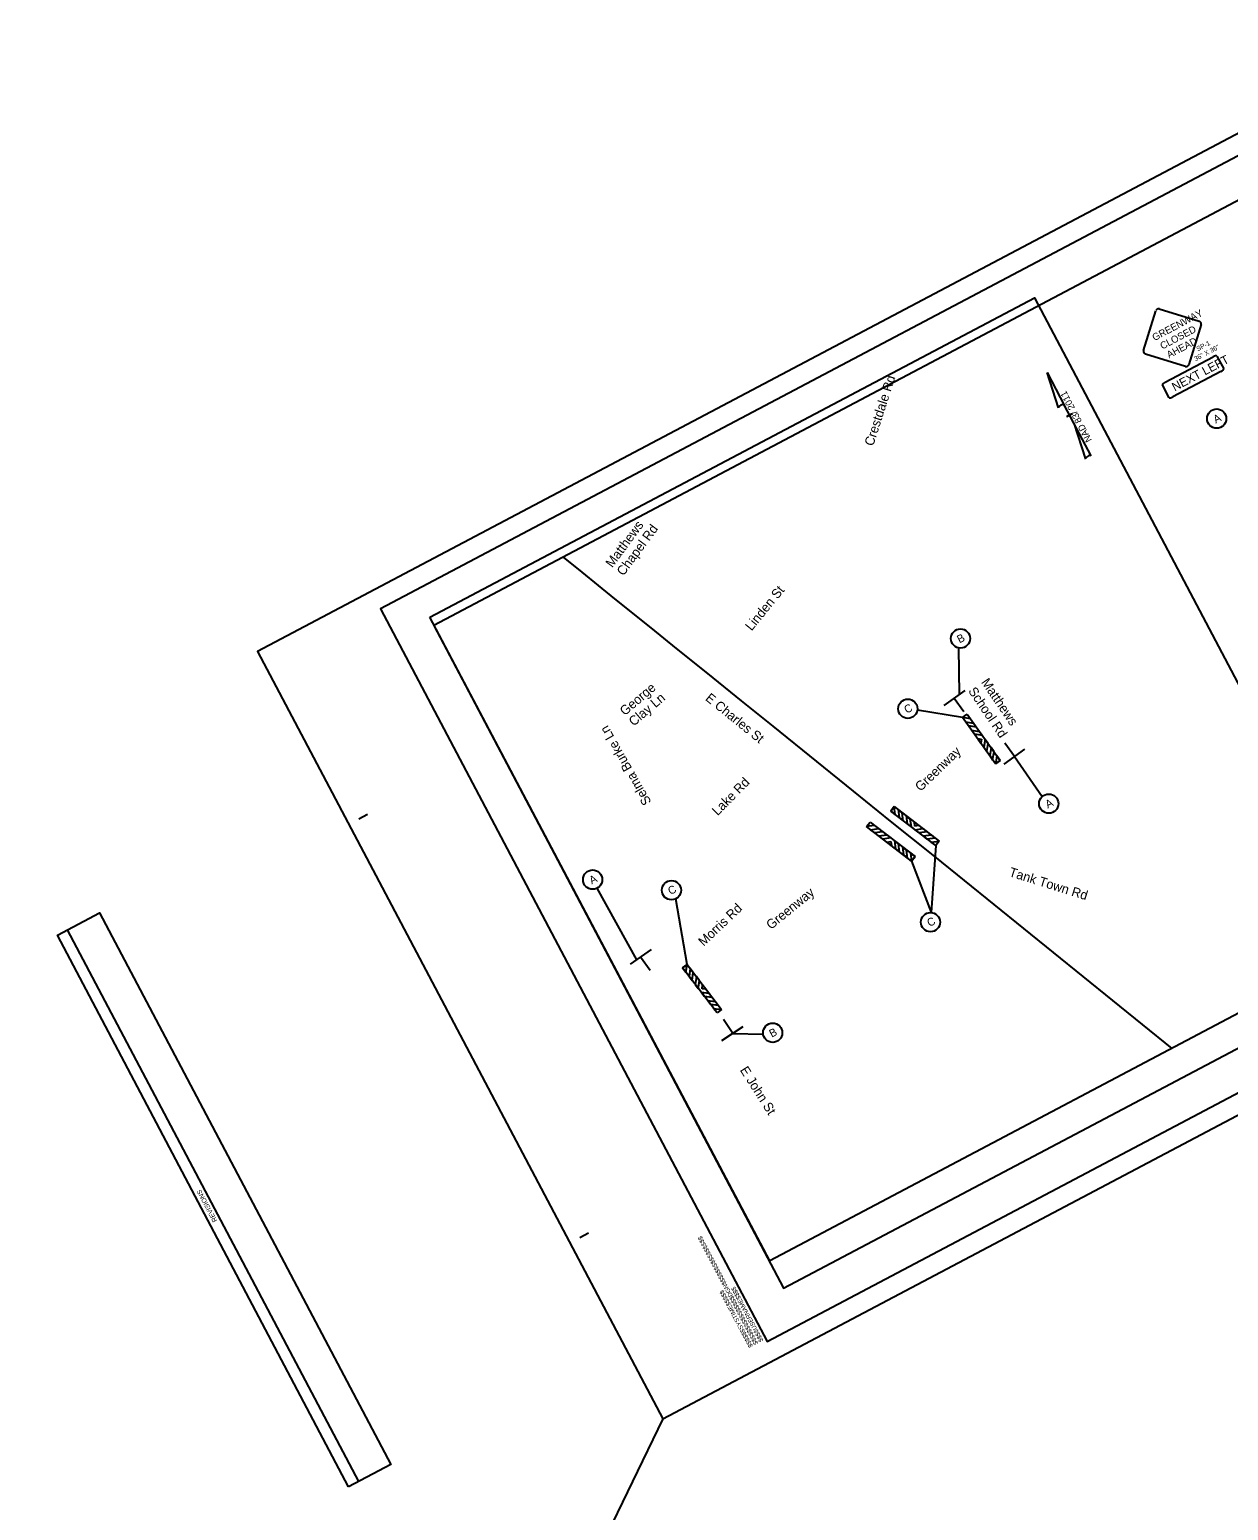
# Model space of a CAD drawing. Extents: x 1485914 to 1489436, y 493744 to 499689.
# Drawn here: x 1487141 to 1488661, y 497812 to 499689 of the extents above; entities that cross this region are included whole.
import ezdxf

# ---------------------------------------------------------------- set-up
doc = ezdxf.new("R2010")
doc.units = 0
for name, color, linetype in [('Default', 7, 'Continuous'), ('DEV BORDER CELL', 7, 'Continuous'), ('DEV STATIONARY SIGN CELL', 7, 'Continuous'), ('DEV TYPE 3 BARRICADE CELL', 7, 'Continuous'), ('Gray Area Fill Shapes', 7, 'Continuous'), ('Old_Level_10', 7, 'Continuous'), ('Prop North Arrow NAD83 for Plan Sheets CELL', 7, 'Continuous'), ('Scratch_Level_0', 7, 'Continuous'), ('Scratch_Level_6', 7, 'Continuous'), ('Sheet Block Revision CELL', 7, 'Continuous'), ('Sheet Plot Border Outside CELL', 7, 'Continuous'), ('WS SP-200 CELL', 7, 'Continuous'), ('WS SP-4L CELL', 7, 'Continuous'), ('WZ OSDR CELL', 7, 'Continuous')]:
    doc.layers.add(name, color=color, linetype=linetype)

msp = doc.modelspace()

# ---------------------------------------------------------------- linework, layer by layer
at = {"layer": 'DEV BORDER CELL'}
for p, q in [((1487586.4, 498954.8), (1487586.4, 498954.8)), ((1487558.1, 498688.3), (1487569.2, 498694.1)), ((1487838.3, 498157.7), (1487849.3, 498163.5)), ((1488075.8, 498025.9), (1488075.8, 498025.9))]:
    msp.add_line(p, q, dxfattribs=at)
msp.add_lwpolyline([(1488912, 499654.8), (1487585.5, 498954.4), (1488075.8, 498025.9), (1489402.2, 498726.3)], close=True, dxfattribs=at)
at = {"layer": 'DEV STATIONARY SIGN CELL'}
for p, q in [((1488326.3, 498850.7), (1488299.9, 498831.9)), ((1488313, 498841.2), (1488325.1, 498824.1)), ((1488376.1, 498757.6), (1488402.5, 498776.4)), ((1488389.4, 498767.1), (1488377.2, 498784.2)), ((1487928.5, 498522.8), (1487902.1, 498504.1)), ((1487915.2, 498513.4), (1487927.3, 498496.3)), ((1488032.1, 498416.1), (1488020.6, 498433.7)), ((1488018.4, 498407.2), (1488045.5, 498424.9))]:
    msp.add_line(p, q, dxfattribs=at)
at = {"layer": 'DEV TYPE 3 BARRICADE CELL'}
for p, q in [((1488323.6, 498816.5), (1488329.5, 498820.7)), ((1488323.6, 498816.5), (1488329.5, 498820.7)), ((1488333.6, 498815), (1488323.6, 498816.5)), ((1488365.4, 498758), (1488323.6, 498816.5)), ((1488327.4, 498811.3), (1488337.4, 498809.7)), ((1488331.1, 498806), (1488327.4, 498811.3)), ((1488329.5, 498820.7), (1488333.6, 498815)), ((1488329.5, 498820.7), (1488371.2, 498762.1)), ((1488341.1, 498804.4), (1488331.1, 498806)), ((1488337.4, 498809.7), (1488341.1, 498804.4)), ((1488334.9, 498800.7), (1488344.9, 498799.1)), ((1488338.6, 498795.5), (1488334.9, 498800.7)), ((1488348.6, 498793.9), (1488338.6, 498795.5)), ((1488342.4, 498790.2), (1488347.5, 498789.4)), ((1488346.2, 498784.9), (1488342.4, 498790.2)), ((1488342.8, 498789.6), (1488346.6, 498784.3)), ((1488344.9, 498799.1), (1488348.6, 498793.9)), ((1488347.5, 498789.4), (1488346.6, 498784.3)), ((1488352.1, 498789), (1488350.3, 498779)), ((1488355.9, 498783.7), (1488352.1, 498789)), ((1488350.3, 498779), (1488354.1, 498773.8)), ((1488354.1, 498773.8), (1488355.9, 498783.7)), ((1488359.6, 498778.5), (1488357.9, 498768.5)), ((1488357.9, 498768.5), (1488361.6, 498763.2)), ((1488363.4, 498773.2), (1488359.6, 498778.5)), ((1488361.6, 498763.2), (1488363.4, 498773.2)), ((1488367.1, 498767.9), (1488365.4, 498758)), ((1488371.2, 498762.1), (1488367.1, 498767.9)), ((1488371.2, 498762.1), (1488365.4, 498758)), ((1488365.4, 498758), (1488371.2, 498762.1)), ((1488232.4, 498698.1), (1488236.8, 498703.8)), ((1488236.8, 498703.8), (1488232.4, 498698.1)), ((1488289.5, 498654.3), (1488232.4, 498698.1)), ((1488232.4, 498698.1), (1488238, 498693.8)), ((1488236.8, 498703.8), (1488293.9, 498660)), ((1488238, 498693.8), (1488236.8, 498703.8)), ((1488241.9, 498699.9), (1488243.2, 498689.8)), ((1488247.1, 498695.9), (1488241.9, 498699.9)), ((1488248.3, 498685.9), (1488247.1, 498695.9)), ((1488252.2, 498692), (1488253.4, 498681.9)), ((1488257.3, 498688), (1488252.2, 498692)), ((1488201.9, 498678.4), (1488206.2, 498684.1)), ((1488201.9, 498678.4), (1488206.2, 498684.1)), ((1488211.9, 498679.8), (1488201.9, 498678.4)), ((1488258.9, 498634.6), (1488201.9, 498678.4)), ((1488206.2, 498684.1), (1488211.9, 498679.8)), ((1488206.2, 498684.1), (1488263.3, 498640.3)), ((1488207, 498674.4), (1488217, 498675.8)), ((1488212.1, 498670.5), (1488207, 498674.4)), ((1488217, 498675.8), (1488222.1, 498671.9)), ((1488243.2, 498689.8), (1488248.3, 498685.9)), ((1488253.4, 498681.9), (1488258.6, 498678)), ((1488258.6, 498678), (1488257.3, 498688)), ((1488267.6, 498680.2), (1488262.5, 498684.1)), ((1488263.1, 498679), (1488262.5, 498684.1)), ((1488263.1, 498683.6), (1488268.2, 498679.7)), ((1488268.2, 498679.7), (1488263.1, 498679)), ((1488263.3, 498674.4), (1488273.3, 498675.8)), ((1488268.5, 498670.4), (1488263.3, 498674.4)), ((1488273.3, 498675.8), (1488278.5, 498671.8)), ((1488222.1, 498671.9), (1488212.1, 498670.5)), ((1488217.3, 498666.5), (1488227.3, 498667.9)), ((1488222.4, 498662.6), (1488217.3, 498666.5)), ((1488232.4, 498664), (1488222.4, 498662.6)), ((1488227.3, 498667.9), (1488232.4, 498664)), ((1488227.5, 498658.7), (1488232.6, 498659.4)), ((1488232.7, 498654.7), (1488227.5, 498658.7)), ((1488228.1, 498658.2), (1488233.3, 498654.3)), ((1488232.6, 498659.4), (1488233.3, 498654.3)), ((1488242.3, 498656.4), (1488237.2, 498660.4)), ((1488237.2, 498660.4), (1488238.4, 498650.3)), ((1488243.5, 498646.4), (1488242.3, 498656.4)), ((1488278.5, 498671.8), (1488268.5, 498670.4)), ((1488273.6, 498666.5), (1488283.6, 498667.9)), ((1488278.7, 498662.5), (1488273.6, 498666.5)), ((1488288.7, 498663.9), (1488278.7, 498662.5)), ((1488283.6, 498667.9), (1488288.7, 498663.9)), ((1488283.9, 498658.6), (1488293.9, 498660)), ((1488289.5, 498654.3), (1488283.9, 498658.6)), ((1488293.9, 498660), (1488289.5, 498654.3)), ((1488293.9, 498660), (1488289.5, 498654.3)), ((1488238.4, 498650.3), (1488243.5, 498646.4)), ((1488252.6, 498648.5), (1488247.4, 498652.5)), ((1488247.4, 498652.5), (1488248.7, 498642.5)), ((1488248.7, 498642.5), (1488253.8, 498638.5)), ((1488253.8, 498638.5), (1488252.6, 498648.5)), ((1488263.3, 498640.3), (1488257.7, 498644.6)), ((1488257.7, 498644.6), (1488258.9, 498634.6)), ((1488263.3, 498640.3), (1488258.9, 498634.6)), ((1488258.9, 498634.6), (1488263.3, 498640.3)), ((1487968.5, 498499.3), (1487974.2, 498503.7)), ((1487974.2, 498503.7), (1487968.5, 498499.3)), ((1487972.8, 498493.7), (1487974.2, 498503.7)), ((1487974.2, 498503.7), (1488018, 498446.6)), ((1488012.2, 498442.2), (1487968.5, 498499.3)), ((1487968.5, 498499.3), (1487972.8, 498493.7)), ((1487978.2, 498498.5), (1487976.7, 498488.5)), ((1487976.7, 498488.5), (1487980.7, 498483.4)), ((1487982.1, 498493.4), (1487978.2, 498498.5)), ((1487980.7, 498483.4), (1487982.1, 498493.4)), ((1487986, 498488.3), (1487984.6, 498478.3)), ((1487990, 498483.1), (1487986, 498488.3)), ((1487984.6, 498478.3), (1487988.5, 498473.1)), ((1487988.5, 498473.1), (1487990, 498483.1)), ((1487996.1, 498463.2), (1487992.2, 498468.4)), ((1487992.2, 498468.4), (1488002.2, 498467.1)), ((1487993.2, 498472.9), (1487993.9, 498478)), ((1487998.3, 498472.3), (1487993.2, 498472.9)), ((1487997.8, 498472.8), (1487993.9, 498478)), ((1487994.3, 498477.4), (1487998.3, 498472.3)), ((1488002.2, 498467.1), (1488006.1, 498462)), ((1488006.1, 498462), (1487996.1, 498463.2)), ((1488004, 498452.9), (1488000.1, 498458.1)), ((1488000.1, 498458.1), (1488010.1, 498456.8)), ((1488014, 498451.7), (1488004, 498452.9)), ((1488012.2, 498442.2), (1488007.9, 498447.8)), ((1488007.9, 498447.8), (1488018, 498446.6)), ((1488010.1, 498456.8), (1488014, 498451.7)), ((1488018, 498446.6), (1488012.2, 498442.2)), ((1488018, 498446.6), (1488012.2, 498442.2))]:
    msp.add_line(p, q, dxfattribs=at)
at = {"layer": 'Gray Area Fill Shapes'}
for centre in [(1488645.7, 499195.5), (1488320.9, 498916.8), (1488254.1, 498827.8), (1488432.8, 498707.5), (1487854.5, 498611.2), (1487954.4, 498597.8), (1488282.9, 498557.3), (1488082.8, 498417.1)]:
    msp.add_circle(centre, 12.2, dxfattribs=at)
at = {"layer": 'Old_Level_10'}
msp.add_lwpolyline([(1487817, 499020.1), (1487840.7, 499000.9), (1487882.2, 498967.2), (1487928.2, 498930.2), (1487960.3, 498904.2), (1488000, 498872.4), (1488042.7, 498838), (1488083, 498805.6), (1488138.2, 498760.9), (1488184.9, 498723.3), (1488231.9, 498685.4), (1488288.1, 498640.3), (1488588.8, 498397.2)], dxfattribs=at)
at = {"layer": 'Prop North Arrow NAD83 for Plan Sheets CELL'}
for p, q in [((1488430.6, 499254.1), (1488430.6, 499254)), ((1488430.6, 499254.1), (1488430.6, 499254)), ((1488430.6, 499254.1), (1488452.9, 499211.8)), ((1488445, 499209.2), (1488430.6, 499254)), ((1488464.5, 499189.8), (1488452.3, 499213)), ((1488452.9, 499211.8), (1488452.3, 499213)), ((1488455.6, 499198.2), (1488455.5, 499198.2)), ((1488455.6, 499198.3), (1488462.7, 499202)), ((1488458.7, 499199.9), (1488455.6, 499198.2)), ((1488464.5, 499189.8), (1488479.2, 499144.2)), ((1488486.5, 499148.2), (1488464.5, 499189.8))]:
    msp.add_line(p, q, dxfattribs=at)
for centre, start_param, end_param in [((1488448.9, 499210.7), 0.216388, 2.908219), ((1488483, 499146), 0.201328, 3.141593)]:
    msp.add_ellipse(centre, major_axis=(3.76, 1.95), ratio=0.461098, start_param=start_param, end_param=end_param, dxfattribs=at)
at = {"layer": 'Scratch_Level_0'}
msp.add_lwpolyline([(1488891.1, 499587.2), (1487653.1, 498933.5), (1488096.7, 498093.4), (1488873.8, 498503.8), (1488818.6, 498608.4), (1489279.5, 498851.7)], close=True, dxfattribs=at)
at = {"layer": 'Scratch_Level_6'}
msp.add_line((1487943.3, 497927.7), (1485914.4, 493744.4), dxfattribs=at)
at = {"layer": 'Sheet Block Revision CELL'}
msp.add_line((1487557.9, 497848.3), (1487188.7, 498547.4), dxfattribs=at)
msp.add_lwpolyline([(1487545, 497841.5), (1487175.9, 498540.6), (1487229.4, 498568.9), (1487598.6, 497869.7)], close=True, dxfattribs=at)
at = {"layer": 'Sheet Plot Border Outside CELL'}
msp.add_lwpolyline([(1487943.3, 497927.7), (1489436, 498715.8), (1488922.4, 499688.6), (1487429.7, 498900.4)], close=True, dxfattribs=at)
at = {"layer": 'WS SP-200 CELL'}
msp.add_line((1488626, 499314.6), (1488610.4, 499264), dxfattribs=at)
for points in [[(1488553, 499281.7), (1488568.7, 499332.3)], [(1488573, 499334.7), (1488623.7, 499319)], [(1488606, 499261.7), (1488555.3, 499277.3)]]:
    msp.add_lwpolyline(points, dxfattribs=at)
for centre, start, end in [((1488572, 499331.3), 117.8286, 162.8351), ((1488572, 499331.3), 72.8221, 117.8286), ((1488622.7, 499315.7), 342.8351, 72.8351), ((1488556.4, 499280.7), 162.8351, 252.8351), ((1488607, 499265), 252.8351, 297.8351), ((1488607, 499265), 297.8351, 342.8351)]:
    msp.add_arc(centre, 3.5, start, end, dxfattribs=at)
at = {"layer": 'WS SP-4L CELL'}
msp.add_line((1488645.9, 499274.8), (1488654.6, 499258.4), dxfattribs=at)
for points in [[(1488610.9, 499257.7), (1488641.3, 499273.8)], [(1488580.4, 499241.6), (1488610.9, 499257.7)], [(1488651.1, 499255.2), (1488620.7, 499239.2)], [(1488585.6, 499222), (1488577, 499238.4)], [(1488620.7, 499239.2), (1488590.2, 499223.1)]]:
    msp.add_lwpolyline(points, dxfattribs=at)
for centre, major_axis, start_param, end_param in [((1488641.9, 499272.7), (4.02, 2.12), 0, 1.570796), ((1488650.6, 499256.3), (-4.02, -2.12), 1.570796, 3.141593), ((1488581, 499240.6), (-4.02, -2.12), 4.712162, 6.283185), ((1488589.6, 499224.1), (-4.02, -2.12), 0, 1.570796)]:
    msp.add_ellipse(centre, major_axis=major_axis, ratio=0.269231, start_param=start_param, end_param=end_param, dxfattribs=at)
at = {"layer": 'WZ OSDR CELL'}
for p, q in [((1488319.8, 498846.1), (1488318.8, 498904.7)), ((1488323.3, 498816.6), (1488266.2, 498826)), ((1488389.4, 498767.1), (1488424.6, 498716.7)), ((1488289.5, 498654.3), (1488283.9, 498569.6)), ((1488258.9, 498634.6), (1488283.9, 498569.6)), ((1487859.7, 498600.2), (1487910, 498509.7)), ((1487974.2, 498503.7), (1487960.1, 498587)), ((1488032.1, 498416.1), (1488070.7, 498415.2))]:
    msp.add_line(p, q, dxfattribs=at)
msp.add_lwpolyline([(1487648.1, 498944), (1488414.6, 499348.7), (1488845.5, 498532.7), (1488079, 498128)], close=True, dxfattribs=at)
for centre in [(1488645.7, 499195.5), (1488320.9, 498916.8), (1488254.1, 498827.8), (1488432.8, 498707.5), (1487854.5, 498611.2), (1487954.4, 498597.8), (1488282.9, 498557.3), (1488082.8, 498417.1)]:
    msp.add_circle(centre, 12.2, dxfattribs=at)

# ---------------------------------------------------------------- texts
at = {"layer": 'Default'}
for s, height, rotation, p in [('Crestdale Rd', 11.875, 72.0984, (1488210.1, 499159.9)), ('Matthews ', 11.88, 53.6736, (1487879.4, 499005.8)), ('Chapel Rd', 11.88, 53.6736, (1487893.6, 498995.4)), ('Linden St', 11.87, 50.8225, (1488056, 498925.7)), ('Matthews', 11.88, 304.0634, (1488346.6, 498861.4)), ('George ', 11.88, 40.2694, (1487895.2, 498818.4)), ('Clay Ln', 11.88, 40.2694, (1487906.5, 498805)), ('E Charles St', 11.875, 321.066, (1487996.5, 498839.4)), ('School Rd', 11.88, 304.0634, (1488330.2, 498850.3)), ('Selma Burke Ln', 11.875, 119.6295, (1487929.3, 498709.5)), ('Greenway', 11.88, 43.8242, (1488270.2, 498722.3)), ('Lake Rd', 11.87, 45.2815, (1488012.9, 498691.5)), ('Tank Town Rd', 11.875, 342.6549, (1488381.5, 498615.8)), ('Greenway', 11.88, 39.1177, (1488080.6, 498547.3)), ('Morris Rd', 11.88, 43.598, (1487995.3, 498526.1)), ('E John St', 11.88, 302.4862, (1488040.8, 498369.8))]:
    msp.add_text(s, height=height, rotation=rotation, dxfattribs=at).set_placement(p)
at = {"layer": 'DEV BORDER CELL'}
for s, p in [('$$$$$$$$$$$$$$$$DGN$$$$$$$$$$$$$$$$', (1488064.5, 498023.4)), ('$$$$USERNAME$$$$', (1488071.2, 498026.9)), ('$$$$$$SYSTIME$$$$$', (1488057.8, 498019.9))]:
    msp.add_text(s, height=5.584, rotation=117.8351, dxfattribs=at).set_placement(p)
at = {"layer": 'Prop North Arrow NAD83 for Plan Sheets CELL'}
msp.add_text('NAD 83/ 2011', height=8.5, rotation=117.8111, dxfattribs=at).set_placement((1488487.8, 499168.3))
at = {"layer": 'Sheet Block Revision CELL'}
msp.add_text('REVISIONS', height=6, rotation=117.8351, dxfattribs=at).set_placement((1487378.7, 498179))
at = {"layer": 'WS SP-200 CELL'}
for s, height, p in [('GREENWAY', 9, (1488566.9, 499293.7)), ('CLOSED', 9, (1488576.9, 499282.9)), ('AHEAD', 9, (1488585.3, 499271.7)), ('SP-1', 6, (1488621.9, 499280.8)), ("36'' X 36''", 6, (1488619, 499268.1))]:
    msp.add_text(s, height=height, rotation=27.8351, dxfattribs=at).set_placement(p)
at = {"layer": 'WS SP-4L CELL'}
msp.add_text('NEXT LEFT', height=11, rotation=27.8351, dxfattribs=at).set_placement((1488592.5, 499229.9))
at = {"layer": 'WZ OSDR CELL'}
for s, p in [('A', (1488644.6, 499189.2)), ('B', (1488319.7, 498910.5)), ('C', (1488252.7, 498821.4)), ('A', (1488431.6, 498701.3)), ('A', (1487853.4, 498605)), ('C', (1487953.2, 498591.5)), ('C', (1488281.7, 498551.1)), ('B', (1488081.6, 498410.8))]:
    msp.add_text(s, height=10, rotation=27.8351, dxfattribs=at).set_placement(p)

doc.saveas('drawing.dxf')
